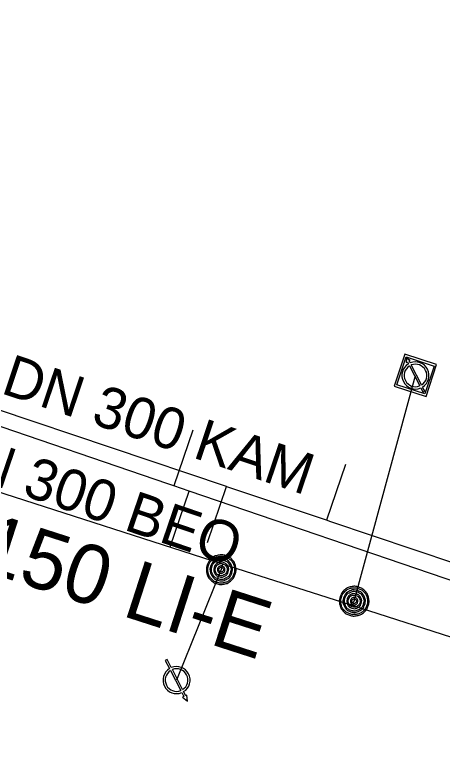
# Model space of a CAD drawing. Extents: x -595129 to -593591, y -1168385 to -1166898.
# Drawn here: x -594711.12 to -594696.64, y -1167146.04 to -1167120.61 of the extents above; entities that cross this region are included whole.
import ezdxf

# ---------------------------------------------------------------- set-up
doc = ezdxf.new("R2010")
doc.units = 0
for name, color, linetype in [('DA Kanalizační stoka popis', 7, 'Continuous'), ('DA V Řad popis', 7, 'Continuous'), ('Default', 7, 'Continuous'), ('Kanalizační přípojka', 7, 'Continuous'), ('Kanalizační stoka', 7, 'Continuous'), ('V Odběrné místo', 7, 'Continuous'), ('V Přípojka', 7, 'Continuous'), ('V Řad', 7, 'Continuous')]:
    doc.layers.add(name, color=color, linetype=linetype)

msp = doc.modelspace()

# ---------------------------------------------------------------- linework, layer by layer
at = {"layer": 'Default'}
for points in [[(-594704.606, -1167139.287), (-594704.567, -1167139.167), (-594704.469, -1167139.073), (-594704.371, -1167138.978), (-594704.236, -1167138.951), (-594704.1, -1167138.923), (-594703.975, -1167138.964), (-594703.852, -1167139.004), (-594703.759, -1167139.103), (-594703.666, -1167139.202), (-594703.639, -1167139.336), (-594703.613, -1167139.47), (-594703.653, -1167139.594), (-594703.693, -1167139.717), (-594703.792, -1167139.81), (-594703.892, -1167139.904), (-594704.025, -1167139.93), (-594704.159, -1167139.956), (-594704.283, -1167139.916), (-594704.407, -1167139.876), (-594704.501, -1167139.775), (-594704.595, -1167139.674), (-594704.62, -1167139.541), (-594704.645, -1167139.407), (-594704.606, -1167139.287)], [(-594704.561, -1167139.301), (-594704.596, -1167139.41), (-594704.574, -1167139.531), (-594704.552, -1167139.652), (-594704.466, -1167139.744), (-594704.381, -1167139.835), (-594704.268, -1167139.872), (-594704.156, -1167139.908), (-594704.035, -1167139.884), (-594703.914, -1167139.86), (-594703.824, -1167139.776), (-594703.734, -1167139.691), (-594703.698, -1167139.579), (-594703.662, -1167139.467), (-594703.685, -1167139.345), (-594703.709, -1167139.224), (-594703.793, -1167139.134), (-594703.878, -1167139.044), (-594703.99, -1167139.008), (-594704.103, -1167138.972), (-594704.226, -1167138.997), (-594704.349, -1167139.022), (-594704.437, -1167139.107), (-594704.526, -1167139.192), (-594704.561, -1167139.301)], [(-594704.487, -1167139.326), (-594704.439, -1167139.175), (-594704.3, -1167139.105), (-594704.162, -1167139.035), (-594704.014, -1167139.083), (-594703.866, -1167139.13), (-594703.795, -1167139.269), (-594703.725, -1167139.407), (-594703.772, -1167139.556), (-594703.82, -1167139.703), (-594703.958, -1167139.774), (-594704.096, -1167139.845), (-594704.244, -1167139.797), (-594704.393, -1167139.749), (-594704.464, -1167139.612), (-594704.535, -1167139.474), (-594704.487, -1167139.326)], [(-594704.443, -1167139.34), (-594704.485, -1167139.47), (-594704.423, -1167139.591), (-594704.361, -1167139.711), (-594704.231, -1167139.753), (-594704.102, -1167139.795), (-594703.981, -1167139.733), (-594703.86, -1167139.671), (-594703.818, -1167139.541), (-594703.776, -1167139.411), (-594703.838, -1167139.291), (-594703.9, -1167139.17), (-594704.03, -1167139.128), (-594704.16, -1167139.086), (-594704.28, -1167139.148), (-594704.401, -1167139.209), (-594704.443, -1167139.34)], [(-594704.368, -1167139.364), (-594704.336, -1167139.264), (-594704.243, -1167139.217), (-594704.151, -1167139.17), (-594704.052, -1167139.202), (-594703.954, -1167139.234), (-594703.907, -1167139.326), (-594703.86, -1167139.418), (-594703.891, -1167139.517), (-594703.923, -1167139.615), (-594704.015, -1167139.663), (-594704.107, -1167139.71), (-594704.206, -1167139.678), (-594704.305, -1167139.646), (-594704.352, -1167139.555), (-594704.4, -1167139.463), (-594704.368, -1167139.364)], [(-594704.324, -1167139.378), (-594704.35, -1167139.458), (-594704.311, -1167139.533), (-594704.273, -1167139.608), (-594704.192, -1167139.634), (-594704.112, -1167139.66), (-594704.037, -1167139.621), (-594703.962, -1167139.583), (-594703.937, -1167139.503), (-594703.911, -1167139.423), (-594703.949, -1167139.348), (-594703.987, -1167139.273), (-594704.068, -1167139.247), (-594704.148, -1167139.221), (-594704.223, -1167139.259), (-594704.298, -1167139.297), (-594704.324, -1167139.378)], [(-594704.249, -1167139.402), (-594704.233, -1167139.352), (-594704.186, -1167139.328), (-594704.14, -1167139.305), (-594704.091, -1167139.321), (-594704.042, -1167139.337), (-594704.018, -1167139.383), (-594703.994, -1167139.429), (-594704.011, -1167139.479), (-594704.026, -1167139.528), (-594704.072, -1167139.551), (-594704.119, -1167139.575), (-594704.168, -1167139.559), (-594704.217, -1167139.543), (-594704.241, -1167139.497), (-594704.265, -1167139.451), (-594704.249, -1167139.402)], [(-594704.204, -1167139.416), (-594704.214, -1167139.447), (-594704.2, -1167139.476), (-594704.185, -1167139.505), (-594704.154, -1167139.515), (-594704.123, -1167139.525), (-594704.094, -1167139.51), (-594704.065, -1167139.495), (-594704.055, -1167139.464), (-594704.045, -1167139.433), (-594704.06, -1167139.404), (-594704.075, -1167139.376), (-594704.106, -1167139.366), (-594704.137, -1167139.356), (-594704.166, -1167139.37), (-594704.194, -1167139.385), (-594704.204, -1167139.416)], [(-594700.096, -1167140.356), (-594700.057, -1167140.236), (-594699.959, -1167140.142), (-594699.861, -1167140.048), (-594699.725, -1167140.021), (-594699.59, -1167139.993), (-594699.465, -1167140.034), (-594699.341, -1167140.074), (-594699.248, -1167140.173), (-594699.155, -1167140.273), (-594699.129, -1167140.406), (-594699.103, -1167140.54), (-594699.143, -1167140.664), (-594699.183, -1167140.788), (-594699.283, -1167140.881), (-594699.382, -1167140.974), (-594699.516, -1167141), (-594699.649, -1167141.026), (-594699.773, -1167140.986), (-594699.898, -1167140.946), (-594699.992, -1167140.845), (-594700.086, -1167140.744), (-594700.11, -1167140.61), (-594700.135, -1167140.477), (-594700.096, -1167140.356)], [(-594700.051, -1167140.371), (-594700.086, -1167140.48), (-594700.064, -1167140.601), (-594700.042, -1167140.722), (-594699.957, -1167140.813), (-594699.872, -1167140.905), (-594699.759, -1167140.942), (-594699.646, -1167140.978), (-594699.526, -1167140.954), (-594699.405, -1167140.931), (-594699.314, -1167140.846), (-594699.224, -1167140.761), (-594699.188, -1167140.65), (-594699.152, -1167140.537), (-594699.175, -1167140.416), (-594699.199, -1167140.294), (-594699.283, -1167140.205), (-594699.367, -1167140.115), (-594699.479, -1167140.078), (-594699.592, -1167140.042), (-594699.715, -1167140.067), (-594699.838, -1167140.092), (-594699.927, -1167140.177), (-594700.016, -1167140.262), (-594700.051, -1167140.371)], [(-594699.977, -1167140.395), (-594699.928, -1167140.245), (-594699.79, -1167140.175), (-594699.652, -1167140.105), (-594699.503, -1167140.153), (-594699.356, -1167140.201), (-594699.285, -1167140.339), (-594699.214, -1167140.477), (-594699.263, -1167140.626), (-594699.31, -1167140.773), (-594699.448, -1167140.844), (-594699.587, -1167140.915), (-594699.735, -1167140.867), (-594699.883, -1167140.819), (-594699.954, -1167140.682), (-594700.025, -1167140.544), (-594699.977, -1167140.395)], [(-594699.933, -1167140.409), (-594699.975, -1167140.54), (-594699.913, -1167140.66), (-594699.852, -1167140.781), (-594699.722, -1167140.823), (-594699.592, -1167140.865), (-594699.471, -1167140.803), (-594699.35, -1167140.742), (-594699.308, -1167140.612), (-594699.266, -1167140.482), (-594699.328, -1167140.361), (-594699.39, -1167140.24), (-594699.52, -1167140.198), (-594699.649, -1167140.156), (-594699.77, -1167140.217), (-594699.891, -1167140.279), (-594699.933, -1167140.409)], [(-594699.858, -1167140.433), (-594699.825, -1167140.333), (-594699.733, -1167140.287), (-594699.641, -1167140.24), (-594699.542, -1167140.272), (-594699.443, -1167140.304), (-594699.396, -1167140.396), (-594699.349, -1167140.488), (-594699.382, -1167140.587), (-594699.413, -1167140.685), (-594699.505, -1167140.733), (-594699.597, -1167140.78), (-594699.696, -1167140.748), (-594699.795, -1167140.716), (-594699.842, -1167140.624), (-594699.89, -1167140.533), (-594699.858, -1167140.433)], [(-594699.814, -1167140.448), (-594699.84, -1167140.528), (-594699.801, -1167140.603), (-594699.763, -1167140.678), (-594699.683, -1167140.704), (-594699.602, -1167140.73), (-594699.527, -1167140.691), (-594699.453, -1167140.653), (-594699.427, -1167140.573), (-594699.401, -1167140.493), (-594699.439, -1167140.418), (-594699.477, -1167140.343), (-594699.558, -1167140.317), (-594699.638, -1167140.291), (-594699.713, -1167140.329), (-594699.788, -1167140.367), (-594699.814, -1167140.448)], [(-594699.739, -1167140.472), (-594699.722, -1167140.422), (-594699.676, -1167140.398), (-594699.63, -1167140.375), (-594699.581, -1167140.391), (-594699.532, -1167140.407), (-594699.508, -1167140.453), (-594699.484, -1167140.499), (-594699.501, -1167140.549), (-594699.516, -1167140.598), (-594699.563, -1167140.621), (-594699.609, -1167140.645), (-594699.658, -1167140.629), (-594699.707, -1167140.613), (-594699.731, -1167140.567), (-594699.755, -1167140.521), (-594699.739, -1167140.472)], [(-594699.694, -1167140.486), (-594699.704, -1167140.517), (-594699.69, -1167140.546), (-594699.675, -1167140.574), (-594699.644, -1167140.585), (-594699.613, -1167140.595), (-594699.584, -1167140.58), (-594699.555, -1167140.565), (-594699.545, -1167140.534), (-594699.535, -1167140.503), (-594699.55, -1167140.474), (-594699.565, -1167140.446), (-594699.596, -1167140.436), (-594699.627, -1167140.426), (-594699.655, -1167140.44), (-594699.684, -1167140.455), (-594699.694, -1167140.486)]]:
    msp.add_open_spline(points, degree=3, dxfattribs=at)
at = {"layer": 'Kanalizační přípojka'}
for points in [[(-594705.095, -1167134.701), (-594705.74, -1167136.594)], [(-594699.915, -1167135.868), (-594700.552, -1167137.764)], [(-594704.591, -1167138.517), (-594703.954, -1167136.621)], [(-594705.856, -1167138.667), (-594705.211, -1167136.774)]]:
    msp.add_lwpolyline(points, dxfattribs=at)
at = {"layer": 'Kanalizační stoka'}
for points in [[(-594677.781, -1167145.419), (-594682.843, -1167143.717), (-594683.031, -1167143.654), (-594684.909, -1167143.023), (-594685.049, -1167142.976), (-594689.819, -1167141.372), (-594689.948, -1167141.329), (-594691.867, -1167140.684), (-594691.929, -1167140.663), (-594700.407, -1167137.813), (-594700.552, -1167137.764), (-594703.933, -1167136.628), (-594703.954, -1167136.621), (-594711.762, -1167133.997), (-594711.791, -1167133.987), (-594715.155, -1167132.856), (-594715.194, -1167132.843), (-594718.784, -1167131.636)], [(-594679.288, -1167145.622), (-594680.083, -1167145.351), (-594680.282, -1167145.283), (-594680.329, -1167145.267), (-594680.48, -1167145.215), (-594687.739, -1167142.737), (-594687.919, -1167142.676), (-594693.067, -1167140.918), (-594693.247, -1167140.857), (-594693.304, -1167140.838), (-594693.474, -1167140.78), (-594694.553, -1167140.412), (-594694.705, -1167140.36), (-594695.812, -1167139.982), (-594696.067, -1167139.895), (-594705.21, -1167136.774), (-594705.474, -1167136.684), (-594705.74, -1167136.594), (-594705.938, -1167136.526), (-594712.43, -1167134.309), (-594712.79, -1167134.186), (-594716.225, -1167133.013), (-594716.566, -1167132.897), (-594717.524, -1167132.57)]]:
    msp.add_lwpolyline(points, dxfattribs=at)
at = {"layer": 'V Odběrné místo'}
for p, q in [((-594697.745, -1167132.524), (-594697.397, -1167133.204)), ((-594697.334, -1167133.171), (-594697.681, -1167132.492)), ((-594705.849, -1167142.866), (-594705.501, -1167143.545)), ((-594705.438, -1167143.513), (-594705.785, -1167142.833))]:
    msp.add_line(p, q, dxfattribs=at)
for points in [[(-594697.172, -1167133.566), (-594696.821, -1167132.481), (-594697.906, -1167132.13), (-594698.257, -1167133.215)], [(-594697.218, -1167133.476), (-594698.167, -1167133.169), (-594697.86, -1167132.22), (-594696.911, -1167132.527)]]:
    msp.add_lwpolyline(points, close=True, dxfattribs=at)
for points in [[(-594697.716, -1167132.424), (-594697.751, -1167132.355), (-594697.715, -1167132.336), (-594697.843, -1167132.259), (-594697.856, -1167132.408), (-594697.815, -1167132.387), (-594697.779, -1167132.456)], [(-594697.362, -1167133.272), (-594697.291, -1167133.412), (-594697.227, -1167133.379), (-594697.299, -1167133.24)], [(-594705.82, -1167142.765), (-594705.963, -1167142.486), (-594706.027, -1167142.519), (-594705.884, -1167142.797)], [(-594705.466, -1167143.614), (-594705.396, -1167143.751), (-594705.439, -1167143.773), (-594705.276, -1167143.907), (-594705.29, -1167143.697), (-594705.332, -1167143.719), (-594705.403, -1167143.581)]]:
    msp.add_lwpolyline(points, dxfattribs=at)
for centre, radius, start, end in [((-594697.539, -1167132.848), 0.46, 121.5511, 292.6053), ((-594697.539, -1167132.848), 0.383, 122.4419, 291.7146), ((-594697.539, -1167132.848), 0.46, 301.5004, 112.6556), ((-594697.539, -1167132.848), 0.383, 302.3911, 111.7116), ((-594705.643, -1167143.189), 0.46, 301.5744, 112.6286), ((-594705.643, -1167143.189), 0.46, 121.5238, 292.6789), ((-594705.643, -1167143.189), 0.383, 122.4145, 291.735), ((-594705.643, -1167143.189), 0.383, 302.4652, 111.7379)]:
    msp.add_arc(centre, radius, start, end, dxfattribs=at)
at = {"layer": 'V Přípojka'}
for points in [[(-594699.76, -1167140.63), (-594699.62, -1167140.51), (-594697.539, -1167132.848)], [(-594704.08, -1167139.25), (-594704.13, -1167139.44), (-594705.643, -1167143.189)]]:
    msp.add_lwpolyline(points, dxfattribs=at)
at = {"layer": 'V Řad'}
msp.add_lwpolyline([(-594632.64, -1167162.29), (-594633.57, -1167161.97), (-594637.055, -1167160.896), (-594646.949, -1167157.654), (-594648.76, -1167157.06), (-594651.956, -1167156.086), (-594663.69, -1167152.24), (-594669.89, -1167150.25), (-594673.67, -1167149), (-594674.04, -1167148.88), (-594682.4, -1167146.2), (-594682.57, -1167146.14), (-594689.71, -1167143.87), (-594691.59, -1167143.26), (-594699.76, -1167140.63), (-594704.08, -1167139.25), (-594711.82, -1167136.77), (-594716.752, -1167135.181), (-594728.089, -1167131.306), (-594729.794, -1167130.778), (-594752.73, -1167123.32), (-594757.82, -1167121.51), (-594758.09, -1167121.3), (-594758.7, -1167120.61)], dxfattribs=at)

# ---------------------------------------------------------------- texts
at = {"layer": 'DA Kanalizační stoka popis'}
for s, rotation, p in [('DN 300 KAM', 341.4256, (-594711.643, -1167133.435)), ('DN 300 BEO', 341.1391, (-594713.973, -1167135.851))]:
    msp.add_text(s, height=1.4, rotation=rotation, dxfattribs=at).set_placement(p)
at = {"layer": 'DA V Řad popis'}
msp.add_text('DN 150 LI-E', height=2, rotation=342.1172, dxfattribs=at).set_placement((-594716.877, -1167137.979))

doc.saveas('drawing.dxf')
